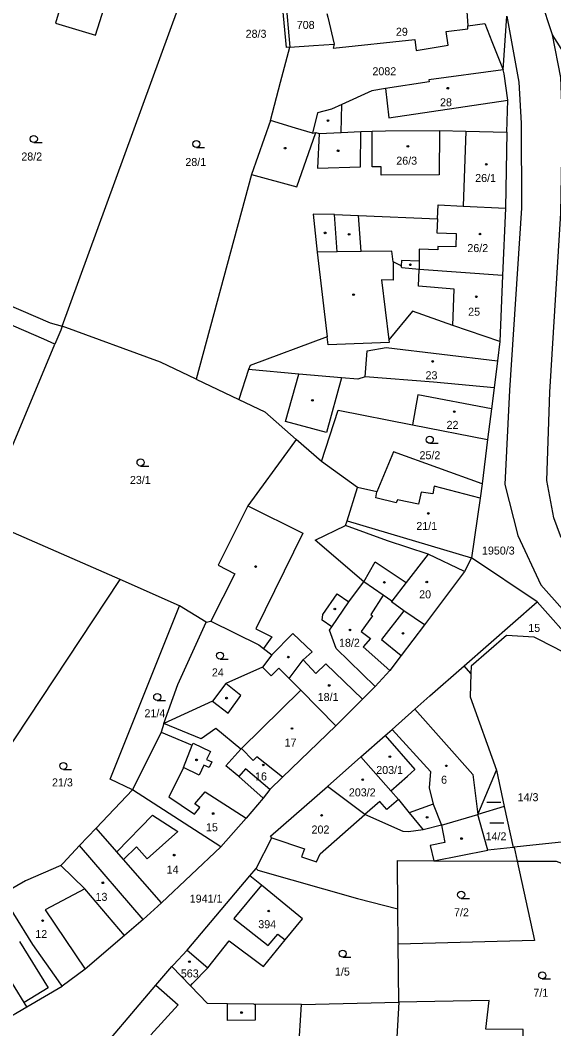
# Model space of a CAD drawing. Extents: x -793666 to -785424, y -1118958 to -1108761.
# Drawn here: x -788273.7 to -788160.3, y -1116813.7 to -1116599.4 of the extents above; entities that cross this region are included whole.
import ezdxf

# ---------------------------------------------------------------- set-up
doc = ezdxf.new("R2010")
doc.units = 0
for name, color, linetype in [('Hranice parcel', 7, 'Continuous'), ('Parcelní čísla', 7, 'Continuous'), ('Vnitřní kresba', 7, 'Continuous'), ('Značky budov', 7, 'Continuous'), ('Značky kultur', 7, 'Continuous')]:
    doc.layers.add(name, color=color, linetype=linetype)

msp = doc.modelspace()

# ---------------------------------------------------------------- linework, layer by layer
at = {"layer": 'Hranice parcel'}
for p, q in [((-788217.45, -1116593.03), (-788216.38, -1116605.15)), ((-788179, -1116594.53), (-788178.58, -1116600.62)), ((-788264.77, -1116664.43), (-788240.19, -1116597.03)), ((-788171.02, -1116609.92), (-788170.26, -1116598.58)), ((-788154.73, -1116611.75), (-788160.53, -1116602.53)), ((-788170.24, -1116623.17), (-788170.57, -1116639.37)), ((-788170.57, -1116639.37), (-788171.2, -1116653.64)), ((-788171.2, -1116653.64), (-788171.72, -1116667.67)), ((-788281.86, -1116705.36), (-788266.33, -1116668.19)), ((-788225.14, -1116673.63), (-788227.24, -1116679.96)), ((-788236.27, -1116675.66), (-788227.24, -1116679.96)), ((-788209.65, -1116693.15), (-788215.02, -1116688.46)), ((-788174.35, -1116688.46), (-788175.54, -1116697.87)), ((-788202.02, -1116698.67), (-788209.65, -1116693.15)), ((-788252.48, -1116718.24), (-788281.86, -1116705.36)), ((-788177.77, -1116713.63), (-788179.26, -1116716.52)), ((-788163.85, -1116722.94), (-788177.77, -1116713.63)), ((-788239.8, -1116723.81), (-788252.48, -1116718.24)), ((-788179.26, -1116716.52), (-788187.79, -1116727.86)), ((-788234.18, -1116727.26), (-788239.8, -1116723.81)), ((-788179.36, -1116736.57), (-788163.85, -1116722.94)), ((-788163.85, -1116722.94), (-788150.62, -1116737.84)), ((-788234.18, -1116727.26), (-788233.17, -1116727.06)), ((-788177.9, -1116738.22), (-788179.36, -1116736.57)), ((-788194.66, -1116750.1), (-788189.82, -1116745.79)), ((-788206.63, -1116749.28), (-788217.91, -1116760.24)), ((-788194.66, -1116750.1), (-788186.51, -1116759.01)), ((-788208.35, -1116762.17), (-788201.27, -1116755.88)), ((-788176.46, -1116768.17), (-788172.48, -1116758.74)), ((-788172.48, -1116758.74), (-788170.82, -1116766.46)), ((-788249.82, -1116762.92), (-788257.57, -1116771.04)), ((-788231.06, -1116775), (-788249.82, -1116762.92)), ((-788170.82, -1116766.46), (-788176.46, -1116768.17)), ((-788170.82, -1116766.46), (-788168.9, -1116775.13)), ((-788184.16, -1116770.4), (-788176.46, -1116768.17)), ((-788184.16, -1116770.4), (-788188.07, -1116771.39)), ((-788231.06, -1116775), (-788243.66, -1116786.93)), ((-788168.9, -1116775.13), (-788168.7, -1116775.11)), ((-788168.7, -1116775.11), (-788168.06, -1116778.04)), ((-788224.89, -1116781.19), (-788223.55, -1116779.64)), ((-788238.21, -1116796.99), (-788224.89, -1116781.19)), ((-788193.34, -1116795.7), (-788193.42, -1116788.17)), ((-788238.21, -1116796.99), (-788233.82, -1116800.7)), ((-788193.21, -1116808), (-788193.34, -1116795.7)), ((-788237.52, -1116804.54), (-788241.47, -1116800.45)), ((-788272.28, -1116808.99), (-788264.8, -1116804.59)), ((-788213.88, -1116808.51), (-788193.21, -1116808)), ((-788215.23, -1116830.01), (-788213.88, -1116808.51))]:
    msp.add_line(p, q, dxfattribs=at)
for points in [[(-788160.53, -1116602.53), (-788163.05, -1116594.97), (-788167.21, -1116587.33), (-788174.52, -1116576.19), (-788191.47, -1116556.73)], [(-788263.13, -1116589.78), (-788266.16, -1116600.03), (-788257.67, -1116602.6), (-788254.43, -1116592.28)], [(-788216.38, -1116605.15), (-788217.1, -1116605.21), (-788218.23, -1116593.2)], [(-788208.52, -1116597.96), (-788208.33, -1116598.74), (-788206.97, -1116604.49)], [(-788178.58, -1116600.62), (-788174.91, -1116600.09), (-788173.42, -1116603.94), (-788171.02, -1116609.92)], [(-788170.26, -1116598.58), (-788167.71, -1116612.57), (-788167.24, -1116621.25), (-788167.14, -1116639.36), (-788169.73, -1116678.01), (-788170.7, -1116698.04), (-788167.95, -1116708.86), (-788163.05, -1116719.36), (-788148.67, -1116735.52), (-788130.05, -1116757.89)], [(-788189.85, -1116603.5), (-788189.51, -1116605.81), (-788182.73, -1116604.74), (-788183.17, -1116601.83)], [(-788183.17, -1116601.83), (-788178.53, -1116601.26), (-788178.58, -1116600.62)], [(-787892.56, -1116976.99), (-787895.19, -1116981.23), (-787941.8, -1116937.65), (-788018.27, -1116866.79), (-788038.98, -1116846.21), (-788057.86, -1116825), (-788078.06, -1116797.96), (-788091.43, -1116783.54), (-788101.65, -1116776.74), (-788123.35, -1116751.89), (-788142.7, -1116729.68), (-788154.86, -1116714.68), (-788158.83, -1116708.96), (-788160.26, -1116705.12), (-788161.73, -1116697.18), (-788161.16, -1116678.39), (-788158.78, -1116640.39), (-788158.44, -1116620.71), (-788158.79, -1116611.56), (-788160.53, -1116602.53)], [(-788216.38, -1116605.15), (-788211.39, -1116604.8), (-788206.97, -1116604.49)], [(-788206.97, -1116604.49), (-788207.17, -1116605.33), (-788189.85, -1116603.5)], [(-788220.51, -1116620.73), (-788218.35, -1116612.59), (-788216.38, -1116605.15)], [(-788171.02, -1116609.92), (-788186.83, -1116612.1), (-788186.77, -1116612.49), (-788196.07, -1116613.9), (-788198.95, -1116614.42), (-788205.34, -1116617.33), (-788207.52, -1116618.32), (-788210.49, -1116619.08), (-788211.54, -1116623.42)], [(-788170.24, -1116623.17), (-788170.05, -1116616.37), (-788170.8, -1116610.77), (-788171.02, -1116609.92)], [(-788220.51, -1116620.73), (-788224.52, -1116632.16), (-788236.27, -1116675.66)], [(-788211.54, -1116623.42), (-788215.21, -1116622.32), (-788220.51, -1116620.73)], [(-788211.54, -1116623.42), (-788210.87, -1116623.28), (-788210.17, -1116623.47), (-788205.48, -1116623.25), (-788201.29, -1116623.06), (-788198.9, -1116622.95)], [(-788184.56, -1116622.83), (-788184.66, -1116632.22), (-788196.96, -1116632.29), (-788196.99, -1116630.55), (-788198.88, -1116630.55), (-788198.9, -1116622.95)], [(-788198.9, -1116622.95), (-788196.05, -1116622.92), (-788184.56, -1116622.83)], [(-788184.56, -1116622.83), (-788178.98, -1116622.96), (-788170.24, -1116623.17)], [(-788266.33, -1116668.19), (-788268.66, -1116667.18), (-788301.6, -1116652.96), (-788357.49, -1116628.83), (-788373.45, -1116634.4)], [(-788206.31, -1116648.63), (-788206.91, -1116640.65), (-788201.76, -1116640.87), (-788184.98, -1116641.58), (-788184.85, -1116638.65), (-788179.57, -1116638.91), (-788170.57, -1116639.37)], [(-788301.21, -1116649.08), (-788267.3, -1116663.67), (-788264.77, -1116664.43)], [(-788206.31, -1116648.63), (-788210.59, -1116648.69), (-788208.47, -1116666.68)], [(-788171.2, -1116653.64), (-788188.91, -1116652.37), (-788192.61, -1116651.98), (-788192.72, -1116651.55), (-788194.45, -1116650.77), (-788194.71, -1116648.47), (-788201.21, -1116648.56), (-788206.31, -1116648.63)], [(-788171.72, -1116667.67), (-788181.71, -1116664.28), (-788190.29, -1116661.22), (-788195.34, -1116667.27), (-788195.26, -1116667.86), (-788208.27, -1116668.37), (-788208.47, -1116666.68)], [(-788264.77, -1116664.43), (-788265.09, -1116665.24), (-788266.33, -1116668.19)], [(-788236.27, -1116675.66), (-788243.89, -1116672.04), (-788264.77, -1116664.43)], [(-788208.47, -1116666.68), (-788224.85, -1116672.76), (-788225.14, -1116673.63)], [(-788171.72, -1116667.67), (-788172.23, -1116671.78), (-788172.95, -1116677.53)], [(-788172.95, -1116677.53), (-788185.87, -1116676.3), (-788200.34, -1116675.2), (-788201.96, -1116675.64), (-788205.41, -1116675.35), (-788214.48, -1116674.6), (-788225.14, -1116673.63)], [(-788172.95, -1116677.53), (-788173.52, -1116681.97), (-788174.35, -1116688.46)], [(-788227.24, -1116679.96), (-788221.72, -1116682.62), (-788215.02, -1116688.46)], [(-788209.65, -1116693.15), (-788206.13, -1116682.27), (-788190.33, -1116685.36), (-788174.35, -1116688.46)], [(-788215.02, -1116688.46), (-788216.31, -1116690.24), (-788225.28, -1116702.55), (-788231.63, -1116715.2), (-788228.1, -1116716.98), (-788233.17, -1116727.06)], [(-788175.54, -1116697.87), (-788194.32, -1116691.08), (-788197.86, -1116699.56), (-788202.02, -1116698.67)], [(-788204.55, -1116706.77), (-788204.23, -1116705.76), (-788202.02, -1116698.67)], [(-788175.54, -1116697.87), (-788175.93, -1116700.94), (-788177.77, -1116713.63)], [(-788200.64, -1116718.69), (-788210.97, -1116709.83), (-788204.55, -1116706.77)], [(-788179.26, -1116716.52), (-788187, -1116712.83), (-788195.65, -1116710.01), (-788204.55, -1116706.77)], [(-788297, -1116785.49), (-788252.62, -1116718.45), (-788252.48, -1116718.24)], [(-788198.26, -1116740.97), (-788206.54, -1116732.89), (-788207.96, -1116728.99), (-788207.47, -1116728.28), (-788203.85, -1116722.97), (-788203.5, -1116722.46), (-788200.64, -1116718.69)], [(-788187.79, -1116727.86), (-788192.16, -1116724.86), (-788194.81, -1116722.96), (-788194.72, -1116722.83), (-788196.58, -1116721.58), (-788200.64, -1116718.69)], [(-788249.82, -1116762.92), (-788254.54, -1116760.6), (-788239.8, -1116723.81)], [(-788243.17, -1116748.78), (-788240.21, -1116740.49), (-788234.18, -1116727.26)], [(-788233.17, -1116727.06), (-788222.99, -1116732.13), (-788222, -1116732.88), (-788220.18, -1116734.25)], [(-788187.79, -1116727.86), (-788192.71, -1116734.33), (-788195.16, -1116737.55), (-788198.26, -1116740.97)], [(-788206.63, -1116749.28), (-788214.02, -1116741.72), (-788216.54, -1116739.25), (-788213.53, -1116735.31), (-788211.66, -1116733.56), (-788215.73, -1116729.71), (-788220.18, -1116734.25)], [(-788150.62, -1116737.84), (-788159.85, -1116732.8), (-788164.47, -1116730.47), (-788170.34, -1116730.13), (-788177.85, -1116736.6), (-788177.9, -1116738.22)], [(-788220.18, -1116734.25), (-788222.2, -1116736.84), (-788230.01, -1116740.3), (-788232.81, -1116744.03), (-788243.17, -1116748.78)], [(-788189.82, -1116745.79), (-788186.61, -1116742.93), (-788179.36, -1116736.57)], [(-788177.9, -1116738.22), (-788178.06, -1116743.16), (-788172.48, -1116758.74)], [(-788198.26, -1116740.97), (-788200.92, -1116743.61), (-788206.63, -1116749.28)], [(-788243.17, -1116748.78), (-788243.75, -1116750.68), (-788249.82, -1116762.92)], [(-788226.82, -1116754.24), (-788232.13, -1116749.85), (-788235.22, -1116752.06), (-788243.17, -1116748.78)], [(-788201.27, -1116755.88), (-788196.12, -1116751.37), (-788194.66, -1116750.1)], [(-788222.06, -1116764.64), (-788227.23, -1116760.08), (-788229.99, -1116757.81), (-788226.82, -1116754.24)], [(-788217.91, -1116760.24), (-788223.38, -1116755.9), (-788224.17, -1116756.67), (-788226.68, -1116754.1), (-788226.82, -1116754.24)], [(-788201.27, -1116755.88), (-788194.93, -1116763.08), (-788193.32, -1116764.92)], [(-788186.51, -1116759.01), (-788186.76, -1116762.5), (-788185.93, -1116765.94), (-788184.16, -1116770.4)], [(-788217.91, -1116760.24), (-788220.64, -1116762.83), (-788222.06, -1116764.64)], [(-788223.55, -1116779.64), (-788220.19, -1116773.09), (-788220.52, -1116772.71), (-788208.35, -1116762.17)], [(-788188.07, -1116771.39), (-788191.13, -1116771.8), (-788192.33, -1116771.73), (-788200.42, -1116768.17), (-788208.35, -1116762.17)], [(-788222.06, -1116764.64), (-788225.66, -1116768.92), (-788231.06, -1116775)], [(-788193.32, -1116764.92), (-788191.01, -1116767.76), (-788188.07, -1116771.39)], [(-788168.9, -1116775.13), (-788174.32, -1116775.72), (-788174.45, -1116775.24), (-788176.46, -1116768.17)], [(-788257.57, -1116771.04), (-788261.06, -1116774.74), (-788264.57, -1116778.47), (-788265.05, -1116778.98)], [(-788243.66, -1116786.93), (-788251.77, -1116777.67), (-788253.15, -1116776.09), (-788257.57, -1116771.04)], [(-788155.32, -1116773.64), (-788166.71, -1116774.89), (-788168.7, -1116775.11)], [(-788193.42, -1116788.17), (-788193.53, -1116777.93), (-788185.76, -1116777.97), (-788168.06, -1116778.04)], [(-788168.06, -1116778.04), (-788164.35, -1116794.89), (-788193.34, -1116795.7)], [(-788168.06, -1116778.04), (-788159.81, -1116778.04), (-788147.84, -1116782.59), (-788145.53, -1116783.68), (-788148.95, -1116819.33)], [(-788265.05, -1116778.98), (-788272.59, -1116782.24), (-788277.6, -1116785.1)], [(-788251.53, -1116793.83), (-788259.93, -1116783.93), (-788265.05, -1116778.98)], [(-788223.55, -1116779.64), (-788223.21, -1116779.95), (-788202.01, -1116786), (-788193.42, -1116788.17)], [(-788233.82, -1116800.7), (-788229.26, -1116794.99), (-788222, -1116800.45), (-788217.39, -1116794.78), (-788213.71, -1116790.33), (-788215.28, -1116789.05), (-788222.43, -1116783.12), (-788224.89, -1116781.19)], [(-788264.8, -1116804.59), (-788265.57, -1116803.49), (-788270.98, -1116795.78), (-788275.03, -1116789.24), (-788277.6, -1116785.1)], [(-788272.28, -1116808.99), (-788272.83, -1116808.09), (-788284.38, -1116789.4), (-788284.62, -1116789.01)], [(-788243.66, -1116786.93), (-788247.59, -1116790.45), (-788251.53, -1116793.83)], [(-788251.53, -1116793.83), (-788259.88, -1116800.99), (-788264.8, -1116804.59)], [(-788241.47, -1116800.45), (-788241.14, -1116800.08), (-788238.21, -1116796.99)], [(-788259.4, -1116821.53), (-788244.9, -1116804.37), (-788241.47, -1116800.45)], [(-788237.52, -1116804.54), (-788237.05, -1116804.04), (-788233.82, -1116800.7)], [(-788213.88, -1116808.51), (-788224.04, -1116808.4), (-788229.65, -1116808.33), (-788233.9, -1116808.29), (-788237.52, -1116804.54)], [(-788193.21, -1116808), (-788194.63, -1116832.82), (-788196.35, -1116832.72), (-788196.49, -1116835.08), (-788197.06, -1116845.13), (-788198.15, -1116845.07), (-788198.52, -1116850.18), (-788199.59, -1116852.67)], [(-788166.76, -1116819.32), (-788166.76, -1116813.8), (-788174.7, -1116813.74), (-788174.01, -1116807.68), (-788193.21, -1116808)], [(-788291.51, -1116815.24), (-788280.71, -1116814.03), (-788277.59, -1116812.09), (-788272.28, -1116808.99)]]:
    msp.add_lwpolyline(points, dxfattribs=at)
at = {"layer": 'Vnitřní kresba'}
for p, q in [((-788196.07, -1116613.9), (-788195.35, -1116620.15)), ((-788205.48, -1116623.25), (-788205.34, -1116617.33)), ((-788195.35, -1116620.15), (-788170.05, -1116616.37)), ((-788214.89, -1116634.83), (-788210.87, -1116623.28)), ((-788210.17, -1116623.47), (-788210.53, -1116630.85)), ((-788201.37, -1116630.57), (-788201.29, -1116623.06)), ((-788178.98, -1116622.96), (-788179.57, -1116638.91)), ((-788224.52, -1116632.16), (-788214.89, -1116634.83)), ((-788210.53, -1116630.85), (-788201.37, -1116630.57)), ((-788206.91, -1116640.65), (-788211.41, -1116640.58)), ((-788211.41, -1116640.58), (-788210.59, -1116648.69)), ((-788201.21, -1116648.56), (-788201.76, -1116640.87)), ((-788184.98, -1116641.58), (-788185.11, -1116644.58)), ((-788185.11, -1116644.58), (-788181.02, -1116644.7)), ((-788181.02, -1116644.7), (-788181.11, -1116647.56)), ((-788184.9, -1116647.45), (-788184.92, -1116648.17)), ((-788181.11, -1116647.56), (-788184.9, -1116647.45)), ((-788188.93, -1116648.06), (-788188.92, -1116650.59)), ((-788184.92, -1116648.17), (-788188.93, -1116648.06)), ((-788194.45, -1116650.77), (-788194.43, -1116654.62)), ((-788192.68, -1116650.46), (-788192.72, -1116651.55)), ((-788188.92, -1116650.59), (-788192.68, -1116650.46)), ((-788188.92, -1116650.59), (-788188.91, -1116652.37)), ((-788189.03, -1116655.93), (-788188.91, -1116652.37)), ((-788194.43, -1116654.62), (-788196.92, -1116654.58)), ((-788196.92, -1116654.58), (-788195.34, -1116667.27)), ((-788181.45, -1116656.56), (-788189.03, -1116655.93)), ((-788181.71, -1116664.28), (-788181.45, -1116656.56)), ((-788199.92, -1116669.66), (-788195.94, -1116668.92)), ((-788195.94, -1116668.92), (-788172.23, -1116671.78)), ((-788200.34, -1116675.2), (-788199.92, -1116669.66)), ((-788217.32, -1116684.65), (-788214.48, -1116674.6)), ((-788205.41, -1116675.35), (-788208.6, -1116686.99)), ((-788189.19, -1116679.02), (-788190.33, -1116685.36)), ((-788173.52, -1116681.97), (-788189.19, -1116679.02)), ((-788208.6, -1116686.99), (-788217.32, -1116684.65)), ((-788185.69, -1116698.4), (-788186.02, -1116699.99)), ((-788175.93, -1116700.94), (-788185.69, -1116698.4)), ((-788198.14, -1116700.86), (-788197.86, -1116699.56)), ((-788193.78, -1116701.95), (-788198.14, -1116700.86)), ((-788188.47, -1116699.68), (-788189.07, -1116702.2)), ((-788186.02, -1116699.99), (-788188.47, -1116699.68)), ((-788225.28, -1116702.55), (-788213.62, -1116708.39)), ((-788193.5, -1116701.28), (-788193.78, -1116701.95)), ((-788189.07, -1116702.2), (-788193.5, -1116701.28)), ((-788204.23, -1116705.76), (-788177.77, -1116713.63)), ((-788213.62, -1116708.39), (-788223.63, -1116728.72)), ((-788187, -1116712.83), (-788191.65, -1116718.85)), ((-788200.64, -1116718.69), (-788198.22, -1116714.48)), ((-788198.22, -1116714.48), (-788191.65, -1116718.85)), ((-788191.65, -1116718.85), (-788194.72, -1116722.83)), ((-788209.34, -1116725.63), (-788206.35, -1116721.25)), ((-788206.35, -1116721.25), (-788203.85, -1116722.97)), ((-788196.58, -1116721.58), (-788199.19, -1116725.66)), ((-788209.53, -1116726.87), (-788209.34, -1116725.63)), ((-788207.47, -1116728.28), (-788209.53, -1116726.87)), ((-788198.78, -1116725.92), (-788201.25, -1116729.23)), ((-788199.19, -1116725.66), (-788198.78, -1116725.92)), ((-788192.16, -1116724.86), (-788196.93, -1116730.93)), ((-788223.63, -1116728.72), (-788220.23, -1116730.41)), ((-788220.23, -1116730.41), (-788222, -1116732.88)), ((-788201.25, -1116729.23), (-788199.23, -1116730.74)), ((-788199.23, -1116730.74), (-788200.81, -1116732.51)), ((-788196.93, -1116730.93), (-788192.71, -1116734.33)), ((-788200.81, -1116732.51), (-788195.16, -1116737.55)), ((-788210.87, -1116738.15), (-788213.53, -1116735.31)), ((-788222.2, -1116736.84), (-788220.33, -1116738.68)), ((-788220.33, -1116738.68), (-788218.71, -1116737.04)), ((-788218.71, -1116737.04), (-788216.54, -1116739.25)), ((-788208.72, -1116736.14), (-788210.87, -1116738.15)), ((-788200.92, -1116743.61), (-788208.72, -1116736.14)), ((-788226.77, -1116742.84), (-788230.01, -1116740.3)), ((-788214.02, -1116741.72), (-788226.68, -1116754.1)), ((-788232.81, -1116744.03), (-788229.5, -1116746.6)), ((-788229.5, -1116746.6), (-788226.77, -1116742.84)), ((-788189.82, -1116745.79), (-788177.47, -1116759.66)), ((-788243.75, -1116750.68), (-788237.13, -1116753.41)), ((-788196.12, -1116751.37), (-788189.8, -1116758.57)), ((-788238.98, -1116758.15), (-788237.13, -1116753.41)), ((-788237.13, -1116753.41), (-788236.96, -1116752.99)), ((-788236.96, -1116752.99), (-788233.26, -1116754.73)), ((-788233.26, -1116754.73), (-788234.08, -1116756.43)), ((-788234.08, -1116756.43), (-788232.98, -1116756.95)), ((-788238.98, -1116758.15), (-788240.57, -1116761.35)), ((-788235.69, -1116759.79), (-788238.98, -1116758.15)), ((-788234.68, -1116757.68), (-788235.69, -1116759.79)), ((-788233.55, -1116758.17), (-788234.68, -1116757.68)), ((-788232.98, -1116756.95), (-788233.55, -1116758.17)), ((-788225.81, -1116758.41), (-788227.23, -1116760.08)), ((-788220.64, -1116762.83), (-788225.81, -1116758.41)), ((-788189.8, -1116758.57), (-788191.41, -1116759.99)), ((-788194.93, -1116763.08), (-788191.41, -1116759.99)), ((-788177.47, -1116759.66), (-788176.46, -1116768.17)), ((-788240.57, -1116761.35), (-788242.1, -1116764.4)), ((-788236.55, -1116765.85), (-788234.38, -1116763.3)), ((-788234.38, -1116763.3), (-788225.66, -1116768.92)), ((-788242.1, -1116764.4), (-788239.51, -1116766.15)), ((-788197.27, -1116765.41), (-788200.42, -1116768.17)), ((-788195.79, -1116767.09), (-788197.27, -1116765.41)), ((-788193.32, -1116764.92), (-788195.79, -1116767.09)), ((-788239.51, -1116766.15), (-788236.67, -1116768.08)), ((-788236.67, -1116768.08), (-788235.54, -1116766.67)), ((-788235.54, -1116766.67), (-788236.55, -1116765.85)), ((-788185.93, -1116765.94), (-788191.01, -1116767.76)), ((-788253.15, -1116776.09), (-788245.58, -1116768.29)), ((-788245.58, -1116768.29), (-788240.22, -1116771.75)), ((-788209.97, -1116776.51), (-788200.42, -1116768.17)), ((-788240.22, -1116771.75), (-788246.73, -1116777.55)), ((-788184.16, -1116770.4), (-788183.44, -1116774.12)), ((-788220.19, -1116773.09), (-788213.29, -1116775.4)), ((-788247.59, -1116790.45), (-788261.06, -1116774.74)), ((-788248.94, -1116775.04), (-788251.77, -1116777.67)), ((-788246.73, -1116777.55), (-788248.94, -1116775.04)), ((-788213.29, -1116775.4), (-788213.87, -1116777.14)), ((-788183.44, -1116774.12), (-788186.53, -1116774.71)), ((-788186.53, -1116774.71), (-788185.76, -1116777.97)), ((-788185.76, -1116777.97), (-788174.32, -1116775.72)), ((-788213.87, -1116777.14), (-788210.71, -1116778.17)), ((-788210.71, -1116778.17), (-788209.97, -1116776.51)), ((-788259.93, -1116783.93), (-788268.37, -1116788.4)), ((-788222.43, -1116783.12), (-788228.27, -1116790.21)), ((-788268.37, -1116788.4), (-788259.88, -1116800.99)), ((-788228.27, -1116790.21), (-788220.97, -1116796)), ((-788273.83, -1116795.1), (-788267.74, -1116804.95)), ((-788220.97, -1116796), (-788218.93, -1116793.53)), ((-788218.93, -1116793.53), (-788217.39, -1116794.78)), ((-788267.74, -1116804.95), (-788272.83, -1116808.09)), ((-788244.9, -1116804.37), (-788240.09, -1116808.55)), ((-788229.6, -1116811.87), (-788229.65, -1116808.33)), ((-788240.09, -1116808.55), (-788245.95, -1116814.96)), ((-788224.04, -1116808.4), (-788223.76, -1116808.53)), ((-788223.76, -1116808.53), (-788223.73, -1116811.81)), ((-788223.73, -1116811.81), (-788229.6, -1116811.87))]:
    msp.add_line(p, q, dxfattribs=at)
at = {"layer": 'Značky budov'}
for centre in [(-788182.82, -1116613.86), (-788208.27, -1116620.72), (-788191.3, -1116626.2), (-788217.38, -1116626.59), (-788206.12, -1116627.15), (-788174.63, -1116630.01), (-788208.88, -1116644.59), (-788203.78, -1116644.89), (-788175.98, -1116644.83), (-788190.77, -1116651.37), (-788202.85, -1116657.71), (-788176.75, -1116658.16), (-788186.02, -1116671.9), (-788211.58, -1116680.17), (-788181.44, -1116682.56), (-788186.95, -1116704.18), (-788223.66, -1116715.47), (-788196.29, -1116718.82), (-788187.28, -1116718.76), (-788206.82, -1116724.47), (-788203.61, -1116728.93), (-788192.34, -1116729.66), (-788216.71, -1116734.7), (-788208.01, -1116740.72), (-788229.84, -1116743.42), (-788215.93, -1116749.87), (-788236.21, -1116756.53), (-788195.12, -1116755.87), (-788222.03, -1116757.62), (-788183.11, -1116757.8), (-788200.9, -1116760.74), (-788232.68, -1116767.93), (-788209.62, -1116768.33), (-788187.2, -1116768.74), (-788179.89, -1116773.25), (-788240.97, -1116776.77), (-788256.13, -1116782.64), (-788220.87, -1116788.65), (-788268.93, -1116790.68), (-788237.72, -1116799.4), (-788226.65, -1116810.21)]:
    msp.add_circle(centre, 0.175, dxfattribs=at)
at = {"layer": 'Značky kultur'}
for p, q in [((-788270.8, -1116625.39), (-788269.05, -1116625.39)), ((-788236.25, -1116626.45), (-788234.5, -1116626.45)), ((-788186.64, -1116689.28), (-788184.89, -1116689.28)), ((-788248.11, -1116694.11), (-788246.36, -1116694.11)), ((-788231.22, -1116735.13), (-788229.47, -1116735.13)), ((-788244.57, -1116743.93), (-788242.82, -1116743.93)), ((-788264.51, -1116758.57), (-788262.76, -1116758.57)), ((-788174.55, -1116765.53), (-788171.55, -1116765.53)), ((-788173.89, -1116769.91), (-788170.89, -1116769.91)), ((-788179.97, -1116785.95), (-788178.22, -1116785.95)), ((-788205.14, -1116798.45), (-788203.39, -1116798.45)), ((-788162.74, -1116803.07), (-788160.99, -1116803.07))]:
    msp.add_line(p, q, dxfattribs=at)
for centre in [(-788270.8, -1116624.64), (-788236.25, -1116625.7), (-788186.64, -1116688.53), (-788248.11, -1116693.36), (-788231.22, -1116734.38), (-788244.57, -1116743.18), (-788264.51, -1116757.82), (-788179.97, -1116785.2), (-788205.14, -1116797.7), (-788162.74, -1116802.32)]:
    msp.add_circle(centre, 0.75, dxfattribs=at)

# ---------------------------------------------------------------- texts
at = {"layer": 'Parcelní čísla'}
for s, p in [('708', (-788214.91, -1116601.26)), ('28/3', (-788225.78, -1116603.14)), ('29', (-788193.84, -1116602.71)), ('2082', (-788198.83, -1116611.1)), ('28', (-788184.46, -1116617.69)), ('28/2', (-788273.45, -1116629.21)), ('26/3', (-788193.76, -1116630.1)), ('28/1', (-788238.59, -1116630.38)), ('26/1', (-788176.99, -1116633.78)), ('26/2', (-788178.65, -1116648.67)), ('25', (-788178.48, -1116662.18)), ('23', (-788187.54, -1116675.68)), ('22', (-788183.07, -1116686.22)), ('25/2', (-788188.82, -1116692.67)), ('23/1', (-788250.37, -1116697.92)), ('21/1', (-788189.5, -1116707.7)), ('1950/3', (-788175.55, -1116712.92)), ('20', (-788188.9, -1116722.22)), ('15', (-788165.71, -1116729.35)), ('18/2', (-788205.93, -1116732.5)), ('24', (-788232.95, -1116738.8)), ('18/1', (-788210.46, -1116744.03)), ('21/4', (-788247.28, -1116747.48)), ('17', (-788217.51, -1116753.72)), ('203/1', (-788198.02, -1116759.53)), ('21/3', (-788266.93, -1116762.17)), ('16', (-788223.78, -1116760.9)), ('6', (-788184.24, -1116761.6)), ('203/2', (-788203.84, -1116764.29)), ('14/3', (-788167.97, -1116765.31)), ('15', (-788234.2, -1116771.7)), ('202', (-788211.77, -1116772.18)), ('14/2', (-788174.78, -1116773.63)), ('14', (-788242.56, -1116780.68)), ('13', (-788257.69, -1116786.48)), ('1941/1', (-788237.66, -1116786.86)), ('7/2', (-788181.49, -1116789.76)), ('394', (-788223.09, -1116792.29)), ('12', (-788270.49, -1116794.38)), ('563', (-788239.55, -1116802.75)), ('1/5', (-788206.79, -1116802.36)), ('7/1', (-788164.62, -1116806.85))]:
    msp.add_text(s, height=1.7, dxfattribs=at).set_placement(p)

doc.saveas('drawing.dxf')
